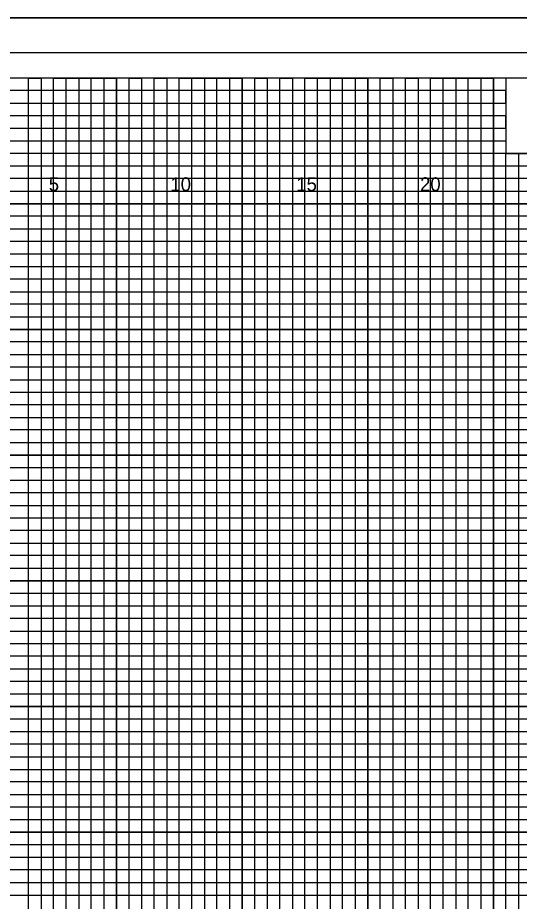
# Model space of a CAD drawing. Extents: x -4 to 103, y -2 to 280.
# Drawn here: x 54.82 to 74.78, y 32.25 to 67.4 of the extents above; entities that cross this region are included whole.
import ezdxf

# ---------------------------------------------------------------- set-up
doc = ezdxf.new("R2010")
doc.units = 0
for name, color, linetype in [('Exist XS Center Line Elevation Label', 7, 'Continuous'), ('Old_Level_63', 7, 'Continuous'), ('Prop XS Dump Level', 7, 'Continuous'), ('Prop XS Pvmt Edge Slope', 7, 'Continuous'), ('Prop XS SE Text', 7, 'Continuous'), ('Sheet Cutting Line CELL', 7, 'Continuous'), ('Sheet Plot Border Inside CELL', 7, 'Continuous'), ('Sheet Plot Border Outside CELL', 7, 'Continuous')]:
    doc.layers.add(name, color=color, linetype=linetype)

msp = doc.modelspace()

# ---------------------------------------------------------------- linework, layer by layer
at = {"layer": 'Exist XS Center Line Elevation Label'}
for points in [[(56.25, 0), (56.25, 65), (58.75, 65), (58.75, 0)], [(61.25, 0), (61.25, 65), (63.75, 65), (63.75, 0)], [(66.25, 0), (66.25, 65), (68.75, 65), (68.75, 0)], [(71.25, 0), (71.25, 65), (73.75, 65), (73.75, 0)], [(0, 62.5), (74.25, 62.5)], [(0, 57.5), (102.5, 57.5), (102.5, 60), (0, 60)], [(0, 52.5), (102.5, 52.5), (102.5, 55), (0, 55)], [(0, 47.5), (102.5, 47.5), (102.5, 50), (0, 50)], [(0, 42.5), (102.5, 42.5), (102.5, 45), (0, 45)], [(0, 37.5), (102.5, 37.5), (102.5, 40), (0, 40)], [(0, 32.5), (102.5, 32.5), (102.5, 35), (0, 35)]]:
    msp.add_lwpolyline(points, dxfattribs=at)
at = {"layer": 'Old_Level_63'}
for points in [[(102.5, 65), (0, 65), (0, 0), (102.5, 0)], [(83.75, 65), (74.25, 65), (74.25, 62), (83.75, 62)]]:
    msp.add_lwpolyline(points, close=True, dxfattribs=at)
at = {"layer": 'Prop XS Dump Level'}
for p, q in [((56.25, 0), (56.25, 65)), ((58.75, 0), (58.75, 65)), ((61.25, 0), (61.25, 65)), ((63.75, 0), (63.75, 65)), ((66.25, 0), (66.25, 65)), ((68.75, 0), (68.75, 65)), ((71.25, 0), (71.25, 65)), ((73.75, 0), (73.75, 65)), ((0, 62.5), (74.25, 62.5)), ((0, 60), (102.5, 60)), ((0, 57.5), (102.5, 57.5)), ((0, 55), (102.5, 55)), ((0, 52.5), (102.5, 52.5)), ((0, 50), (102.5, 50)), ((0, 47.5), (102.5, 47.5)), ((0, 45), (102.5, 45)), ((0, 42.5), (102.5, 42.5)), ((0, 40), (102.5, 40)), ((0, 37.5), (102.5, 37.5)), ((0, 35), (102.5, 35)), ((0, 32.5), (102.5, 32.5))]:
    msp.add_line(p, q, dxfattribs=at)
at = {"layer": 'Prop XS SE Text'}
for points in [[(55.25, 0), (55.25, 65), (55.75, 65), (55.75, 0)], [(56.75, 0), (56.75, 65), (57.25, 65), (57.25, 0)], [(57.75, 0), (57.75, 65), (58.25, 65), (58.25, 0)], [(59.25, 0), (59.25, 65), (59.75, 65), (59.75, 0)], [(60.25, 0), (60.25, 65), (60.75, 65), (60.75, 0)], [(61.75, 0), (61.75, 65), (62.25, 65), (62.25, 0)], [(62.75, 0), (62.75, 65), (63.25, 65), (63.25, 0)], [(64.25, 0), (64.25, 65), (64.75, 65), (64.75, 0)], [(65.25, 0), (65.25, 65), (65.75, 65), (65.75, 0)], [(66.75, 0), (66.75, 65), (67.25, 65), (67.25, 0)], [(67.75, 0), (67.75, 65), (68.25, 65), (68.25, 0)], [(69.25, 0), (69.25, 65)], [(69.25, 65), (69.75, 65), (69.75, 0)], [(70.25, 0), (70.25, 65), (70.75, 65), (70.75, 0)], [(71.75, 0), (71.75, 65), (72.25, 65), (72.25, 0)], [(72.75, 0), (72.75, 65), (73.25, 65), (73.25, 0)], [(0, 62), (0, 63), (74.25, 63), (74.25, 63.5), (0, 63.5), (0, 64), (74.25, 64), (74.25, 64.5), (0, 64.5)], [(0, 61.5), (102.5, 61.5), (102.5, 62), (0, 62)], [(74.25, 0), (74.25, 62), (74.75, 62), (74.75, 0)], [(0, 60.5), (102.5, 60.5), (102.5, 61), (0, 61)], [(0, 59), (102.5, 59), (102.5, 59.5), (0, 59.5)], [(0, 58), (102.5, 58), (102.5, 58.5), (0, 58.5)], [(0, 56.5), (102.5, 56.5), (102.5, 57), (0, 57)], [(0, 55.5), (102.5, 55.5), (102.5, 56), (0, 56)], [(0, 54), (102.5, 54), (102.5, 54.5), (0, 54.5)], [(0, 53), (102.5, 53), (102.5, 53.5), (0, 53.5)], [(0, 51.5), (102.5, 51.5), (102.5, 52), (0, 52)], [(0, 50.5), (102.5, 50.5), (102.5, 51), (0, 51)], [(0, 49), (102.5, 49), (102.5, 49.5), (0, 49.5)], [(0, 48), (102.5, 48), (102.5, 48.5), (0, 48.5)], [(0, 46.5), (102.5, 46.5), (102.5, 47), (0, 47)], [(0, 45.5), (102.5, 45.5), (102.5, 46), (0, 46)], [(0, 44), (102.5, 44), (102.5, 44.5), (0, 44.5)], [(0, 43), (102.5, 43), (102.5, 43.5), (0, 43.5)], [(0, 41.5), (102.5, 41.5), (102.5, 42), (0, 42)], [(0, 40.5), (102.5, 40.5), (102.5, 41), (0, 41)], [(0, 39), (102.5, 39), (102.5, 39.5), (0, 39.5)], [(0, 38), (102.5, 38), (102.5, 38.5), (0, 38.5)], [(0, 36.5), (102.5, 36.5), (102.5, 37), (0, 37)], [(0, 35.5), (102.5, 35.5), (102.5, 36), (0, 36)], [(0, 34), (102.5, 34), (102.5, 34.5), (0, 34.5)], [(0, 33), (102.5, 33), (102.5, 33.5), (0, 33.5)]]:
    msp.add_lwpolyline(points, dxfattribs=at)
at = {"layer": 'Sheet Cutting Line CELL'}
msp.add_line((-3.5, 67.4), (103.4, 67.4), dxfattribs=at)
at = {"layer": 'Sheet Plot Border Inside CELL'}
msp.add_lwpolyline([(103, 66), (-2.8, 66), (-2.8, -1), (103, -1)], close=True, dxfattribs=at)
at = {"layer": 'Sheet Plot Border Outside CELL'}
msp.add_lwpolyline([(103.4, 67.4), (-3.5, 67.4), (-3.5, -2.425), (103.4, -2.425)], close=True, dxfattribs=at)

# ---------------------------------------------------------------- texts
at = {"layer": 'Prop XS Pvmt Edge Slope'}
for s, p in [('5', (56.057, 60.5)), ('10', (60.897, 60.5)), ('15', (65.906, 60.5)), ('20', (70.831, 60.5))]:
    msp.add_text(s, height=0.55, dxfattribs=at).set_placement(p)

doc.saveas('drawing.dxf')
